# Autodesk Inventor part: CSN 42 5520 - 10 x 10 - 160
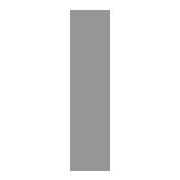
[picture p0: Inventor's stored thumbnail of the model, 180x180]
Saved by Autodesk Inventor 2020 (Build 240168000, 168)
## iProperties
IsCustomPart: 1
Created: 2019-01
Part Number: CSN 42 5520 - 10 x 10 - 160
Material: Ocel, měkká
Description: Tyč
Document SubType Name: Modeling
Standard: CSN 42 5520
Designer: doma
Standards Organization: CSN
Language: cs-CZ
Size Designation: 10 x 10 - 160
Categories: <MemberInstance><Categories><Category DisplayName="Konstrukční profily" InternalName="089c4875-fa83-4c05-b084-43b9cc11f5ed" Mnemonic="GRDR"><CategoryParameter D
Stock Number: 10 x 10
Density: 7.85 g/cm^3
Appearance: Pololeštěná
Mass: 122.563 g
Surface Area: 64.572 cm^2
Volume: 15.6131 cm^3
G_L: 160,000 mm
Author: doma
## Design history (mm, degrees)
node "Počáteční rovina"
node "Koncová rovina"
sketch "Náčrt"
  geometry: L1 (5, -5)-(-5, -5); L2 (-5, -5)-(-5, 5); L3 (-5, 5)-(5, 5); L4 (5, 5)-(5, -5); L5 (-6, 0)-(8, 0); L6 (0, -30)-(0, 40); L7 (0, 54)-(0, -44) reference; L8 (-9.2, 0)-(13.2, 0) reference
  constraints: 12 end point, 2 collinear, 2 parallel, 1 horizontal, 1 perpendicular
  dimensions: "d0" = 10 distance between parallel lines of L3 L1 (= G_W); "d1" = 10 distance between parallel lines of L4 L2 (= G_H); "d4" = 5 distance between parallel lines of L6 L4 (= 0.5 x d1); "d5" = 5 distance between parallel lines of L5 L3 (= 0.5 x d0)
extrude "Těleso" new body sketch "Náčrt" stored distance "d2" = 160 (= G_L); taper "d3" = 0 deg
node "Driven Length"
  sketch "Sketch3"
    geometry: L1 (0, 0)-(10, 0) reference
    constraints: 2 end point, 1 horizontal
  workplane "Work Plane3"
  sketch "Sketch4"
    geometry: L1 (-2, 0)-(12, 0) reference; L2 (-2, 160)-(12, 160) reference
    dimensions: "d9" = 160 distance between parallel lines of L1 L2 (derived)
sketch "Náčrt5"
  geometry: L1 (0, 7)-(-7, 0) reference; L2 (-10, 157.163)-(-131.923, 354.734) reference; L3 (-10, 160)-(-10, 0) reference; L4 (-10, 160)-(0, 160) reference; L5 (-10, 157.163)-(0, 160); L6 (0, 160)-(6.493, 174.726); L7 (6.493, 174.726)-(-36.044, 174.726); L8 (-36.044, 174.726)-(-10, 157.163); L9 (0, 7)-(17.89, 7); L10 (17.89, 7)-(17.89, -17.89); L11 (17.89, -17.89)-(-7, 0); 1 further point
  constraints: 14 end point, 2 point on line, 1 horizontal, 1 parallel, 1 perpendicular
extrude "Vysunutí2" cut sketch "Náčrt5" extent not by distance; stored distance "d10" = 0; taper "d11" = 0 deg
chamfer "Zkosení1" distance "d12" = 2; stored, may be unused: second distance "d13" = 2, angle "d14" = 45 deg
body "Solid1"
node "Referenční1"
node "Referenční2"
other parameters: "G_W" = 10 [user parameter; used in 1 equation term], "G_H" = 10 [user parameter; used in 1 equation term], "G_L" = 160 (= d9) [user parameter; used in 1 equation term], "G_OFFSET_START" = 0 [user parameter; used in 1 equation term], "G_OFFSET_END" = 0 [user parameter; used in 1 equation term], "d6" = 0 (computed from G_OFFSET_START), "d8" = 90 deg
